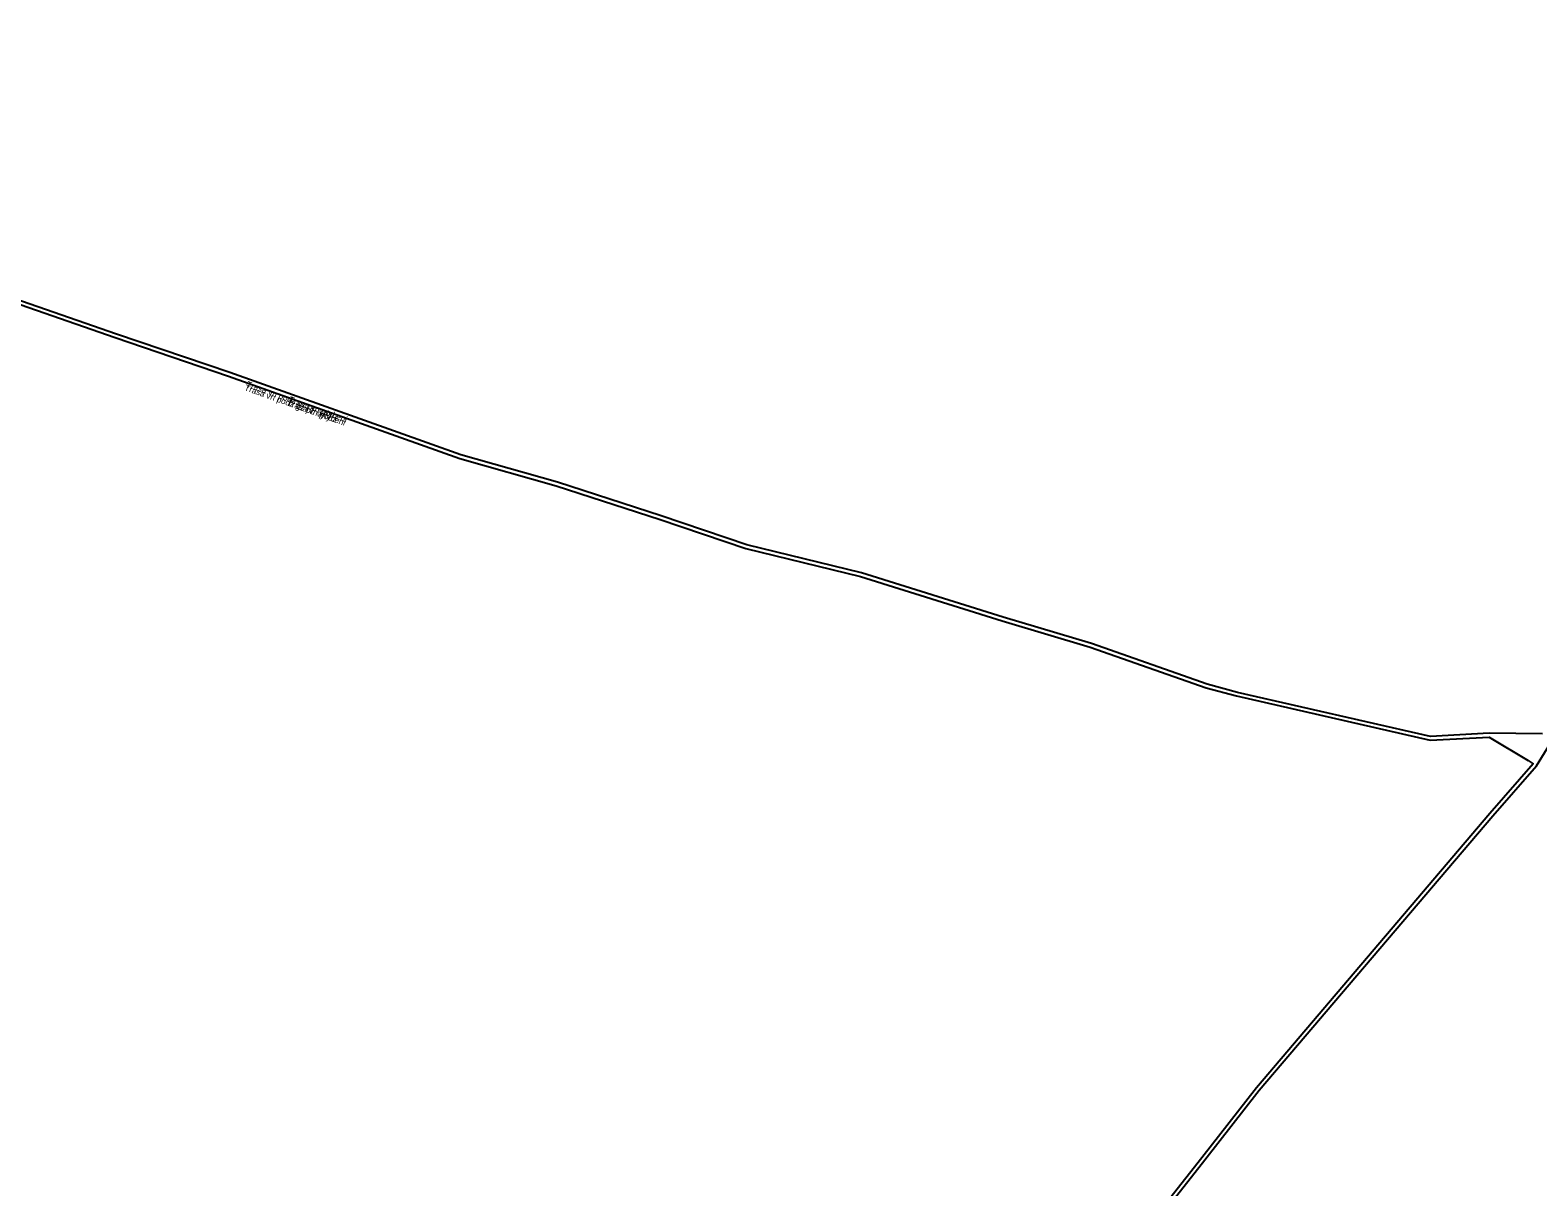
# Model space of a CAD drawing. Extents: x -764385 to -763933, y -1073568 to -1073177.
# Drawn here: x -764268.6 to -764146.1, y -1073462.1 to -1073368.1 of the extents above; entities that cross this region are included whole.
import ezdxf

# ---------------------------------------------------------------- set-up
doc = ezdxf.new("R2010")
doc.units = 0
doc.layers.add('Popiskový text - Ostatní atributy Trasy', color=7, linetype='Continuous')
doc.layers.add('Spojnice VN', color=7, linetype='Continuous')

msp = doc.modelspace()

# ---------------------------------------------------------------- linework, layer by layer
at = {"layer": 'Spojnice VN'}
for points in [[(-764145.67, -1073425.24), (-764150, -1073425.21), (-764154.78, -1073425.46), (-764170.48, -1073421.88), (-764172.94, -1073421.21), (-764182.35, -1073417.92), (-764189.51, -1073415.77), (-764201.05, -1073412.16), (-764210.36, -1073409.89), (-764217.33, -1073407.54), (-764225.77, -1073404.79), (-764233.61, -1073402.58), (-764252.41, -1073395.89), (-764261.62, -1073392.75), (-764277.64, -1073387.2), (-764287.19, -1073382.75), (-764293.84, -1073380.18), (-764307.34, -1073375.12), (-764316.72, -1073371.94), (-764327.72, -1073368.05), (-764330.44, -1073368.57), (-764331.16, -1073370.89), (-764332.19, -1073372.8), (-764335.6, -1073378.49)], [(-764145.67, -1073425.24), (-764150, -1073425.21), (-764154.78, -1073425.46), (-764170.48, -1073421.88), (-764172.94, -1073421.21), (-764182.35, -1073417.92), (-764189.51, -1073415.77), (-764201.05, -1073412.16), (-764210.36, -1073409.89), (-764217.33, -1073407.54), (-764225.77, -1073404.79), (-764233.61, -1073402.58), (-764252.41, -1073395.89), (-764261.62, -1073392.75), (-764277.64, -1073387.2), (-764287.19, -1073382.75), (-764293.84, -1073380.18), (-764307.34, -1073375.12), (-764316.72, -1073371.94), (-764327.72, -1073368.05), (-764330.44, -1073368.57), (-764331.16, -1073370.89), (-764332.19, -1073372.8), (-764335.6, -1073378.49)], [(-764335.6, -1073378.49), (-764331.93, -1073372.94), (-764330.88, -1073371.01), (-764330.21, -1073368.83), (-764327.74, -1073368.36), (-764316.82, -1073372.22), (-764307.44, -1073375.4), (-764293.95, -1073380.46), (-764287.31, -1073383.03), (-764277.75, -1073387.48), (-764261.72, -1073393.03), (-764252.51, -1073396.17), (-764233.7, -1073402.87), (-764225.86, -1073405.08), (-764217.42, -1073407.82), (-764210.44, -1073410.18), (-764201.13, -1073412.45), (-764189.6, -1073416.06), (-764182.44, -1073418.21), (-764173.03, -1073421.5), (-764170.55, -1073422.17), (-764154.81, -1073425.76), (-764150, -1073425.51), (-764146.85, -1073427.43)], [(-764335.6, -1073378.49), (-764331.93, -1073372.94), (-764330.88, -1073371.01), (-764330.21, -1073368.83), (-764327.74, -1073368.36), (-764316.82, -1073372.22), (-764307.44, -1073375.4), (-764293.95, -1073380.46), (-764287.31, -1073383.03), (-764277.75, -1073387.48), (-764261.72, -1073393.03), (-764252.51, -1073396.17), (-764233.7, -1073402.87), (-764225.86, -1073405.08), (-764217.42, -1073407.82), (-764210.44, -1073410.18), (-764201.13, -1073412.45), (-764189.6, -1073416.06), (-764182.44, -1073418.21), (-764173.03, -1073421.5), (-764170.55, -1073422.17), (-764154.81, -1073425.76), (-764150, -1073425.51), (-764146.85, -1073427.43)], [(-764266.24, -1073555.09), (-764265.8, -1073554.12), (-764237.34, -1073513.96), (-764233.09, -1073506.98), (-764221.63, -1073490.29), (-764219.1, -1073485.55), (-764216.37, -1073480.19), (-764215.81, -1073479.9), (-764214.61, -1073480.4), (-764202.66, -1073484.16), (-764197.87, -1073483.53), (-764194.44, -1073483.15), (-764193.22, -1073481.76), (-764187.62, -1073477.73), (-764185.73, -1073474.48), (-764184.47, -1073471.89), (-764180.25, -1073468.96), (-764173.13, -1073459.89), (-764168.7, -1073454.23), (-764149.72, -1073431.92), (-764146.17, -1073427.84), (-764144.57, -1073425.25)], [(-764266.24, -1073555.09), (-764265.8, -1073554.12), (-764237.34, -1073513.96), (-764233.09, -1073506.98), (-764221.63, -1073490.29), (-764219.1, -1073485.55), (-764216.37, -1073480.19), (-764215.81, -1073479.9), (-764214.61, -1073480.4), (-764202.66, -1073484.16), (-764197.87, -1073483.53), (-764194.44, -1073483.15), (-764193.22, -1073481.76), (-764187.62, -1073477.73), (-764185.73, -1073474.48), (-764184.47, -1073471.89), (-764180.25, -1073468.96), (-764173.13, -1073459.89), (-764168.7, -1073454.23), (-764149.72, -1073431.92), (-764146.17, -1073427.84), (-764144.57, -1073425.25)], [(-764146.85, -1073427.43), (-764146.43, -1073427.68), (-764149.95, -1073431.72), (-764168.93, -1073454.04), (-764173.37, -1073459.71), (-764180.46, -1073468.74), (-764184.7, -1073471.69), (-764185.99, -1073474.34), (-764187.85, -1073477.52), (-764193.42, -1073481.54), (-764194.59, -1073482.86), (-764197.91, -1073483.23), (-764202.63, -1073483.85), (-764214.51, -1073480.12), (-764215.82, -1073479.57), (-764216.59, -1073479.97), (-764219.37, -1073485.41), (-764221.89, -1073490.13), (-764233.34, -1073506.82), (-764237.59, -1073513.79), (-764265.99, -1073553.87), (-764272.76, -1073556.1)], [(-764146.85, -1073427.43), (-764146.43, -1073427.68), (-764149.95, -1073431.72), (-764168.93, -1073454.04), (-764173.37, -1073459.71), (-764180.46, -1073468.74), (-764184.7, -1073471.69), (-764185.99, -1073474.34), (-764187.85, -1073477.52), (-764193.42, -1073481.54), (-764194.59, -1073482.86), (-764197.91, -1073483.23), (-764202.63, -1073483.85), (-764214.51, -1073480.12), (-764215.82, -1073479.57), (-764216.59, -1073479.97), (-764219.37, -1073485.41), (-764221.89, -1073490.13), (-764233.34, -1073506.82), (-764237.59, -1073513.79), (-764265.99, -1073553.87), (-764272.76, -1073556.1)]]:
    msp.add_lwpolyline(points, dxfattribs=at)

# ---------------------------------------------------------------- texts
at = {"layer": 'Popiskový text - Ostatní atributy Trasy'}
for s, rotation, p in [('Trasa vn podz gz po vytyceni', 340.4114, (-764251.26, -1073397.31)), ('Trasa vn podz gz po vytyceni', 340.4118, (-764251.11, -1073397.04)), ('Trasa vn podz', 340.4114, (-764247.79, -1073398.54)), ('Trasa vn podz', 340.4118, (-764247.64, -1073398.28))]:
    msp.add_text(s, height=0.5, rotation=rotation, dxfattribs=at).set_placement(p)

doc.saveas('drawing.dxf')
